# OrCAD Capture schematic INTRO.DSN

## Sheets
1 PAGE2: size A; title: test; rev: A; company: EMA Design Automation; note: 1234567890; note: 225 Tech Park Dr.; note: Rochester, NY 14643
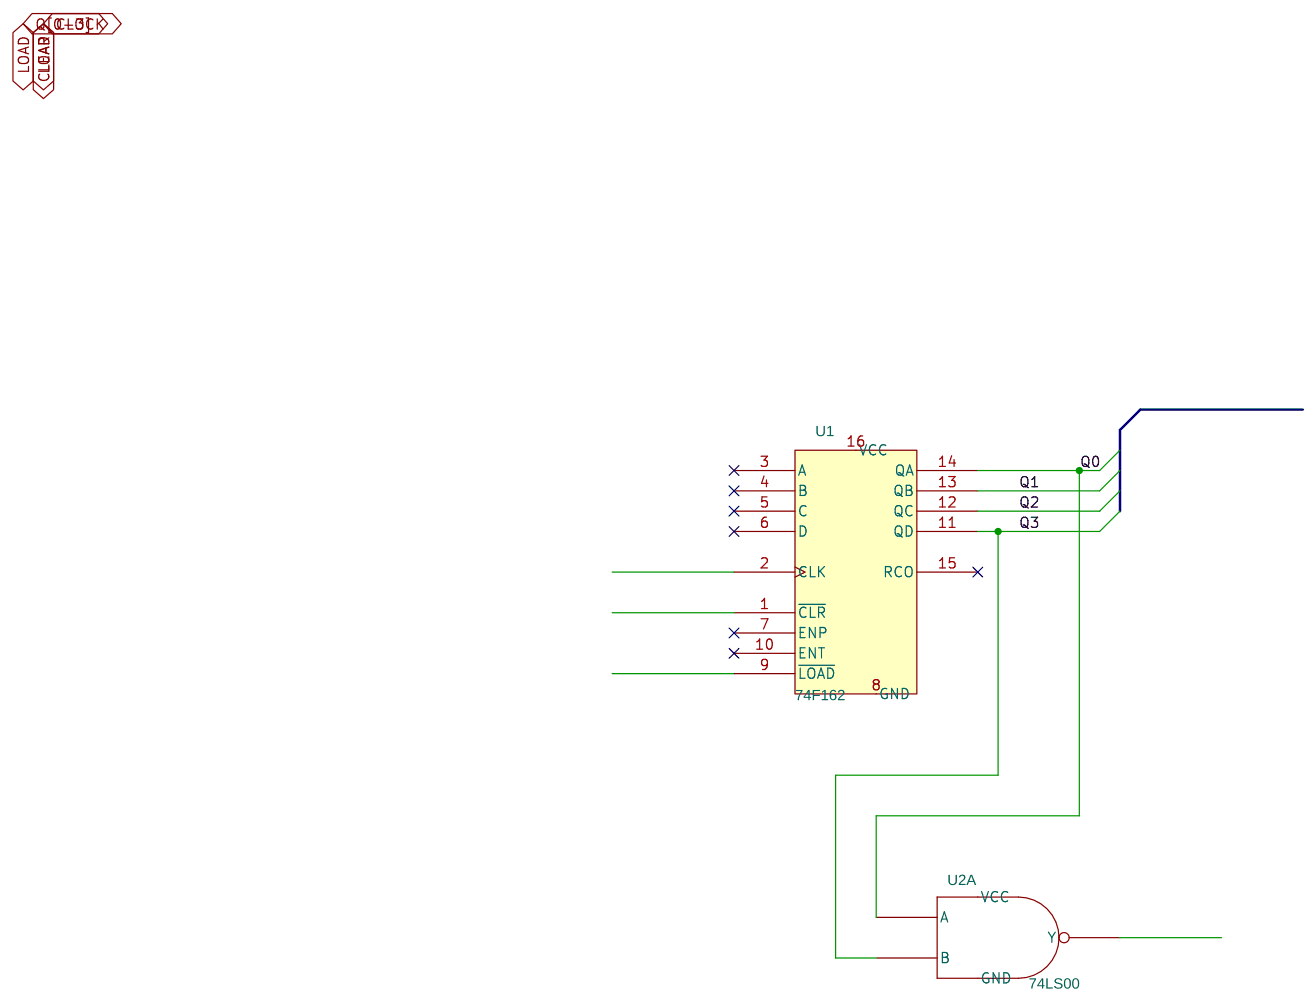
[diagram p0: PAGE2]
2 PAGE1: size A; title: Intro Design; note: Rochester, NY 14623
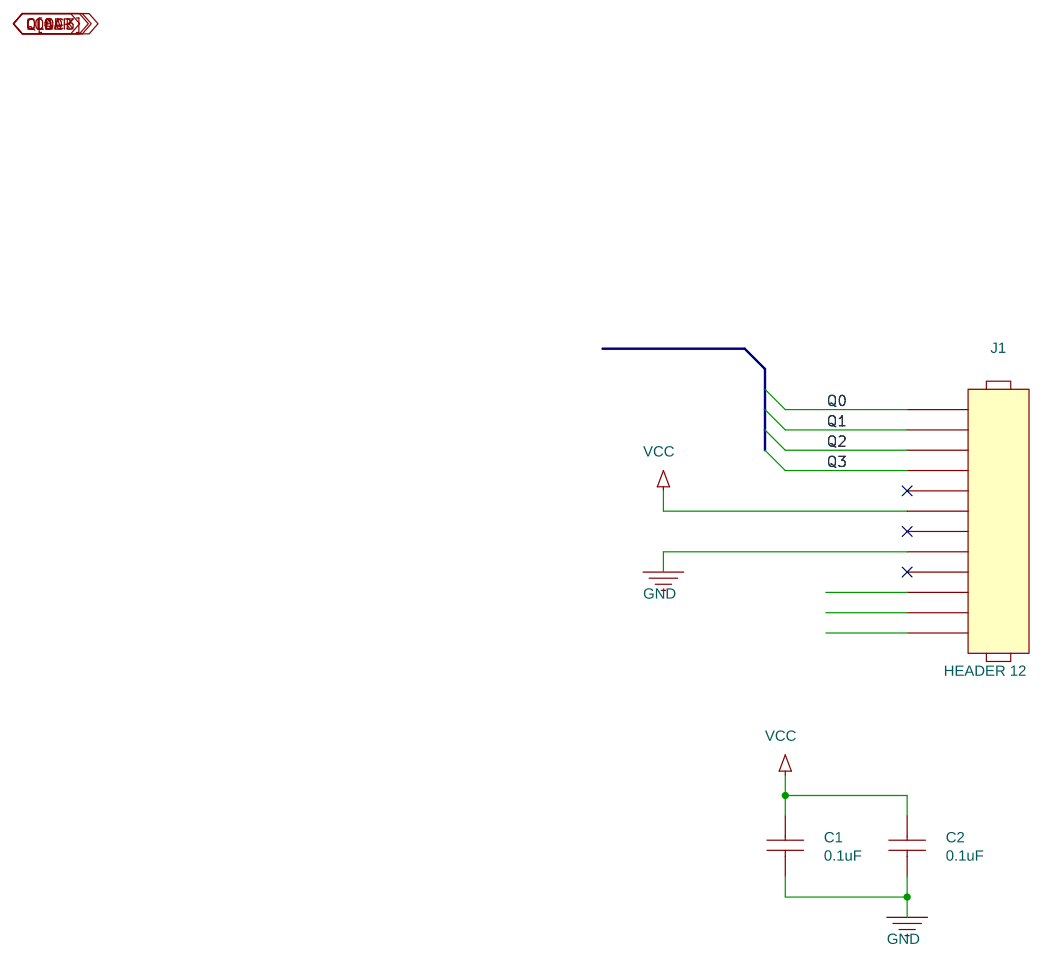
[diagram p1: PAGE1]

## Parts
sheet PAGE1
C1  0.1uF
C2  0.1uF
J1  HEADER 12
sheet PAGE2
U1  74F162
U2  74LS00  (section A)

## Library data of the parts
C1 C2 = CAP_NP
J1 = HEADER_12
U1 = 74F162
U2 = 74LS00

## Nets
GND: C1.2 C2.2 J1.8 U1.8(GND) U2.7(GND)
VCC: C1.1 C2.1 J1.6 U1.16(VCC) U2.14(VCC)
CLEAR: J1.11 U1.1(~{CLR})
CLOCK: J1.12 U1.2(CLK)
LOAD: J1.10 U1.9(~{LOAD}) U2.3(Y)
Q0: J1.1 U1.14(QA) U2.1(A)
Q1: J1.2 U1.13(QB)
Q2: J1.3 U1.12(QC)
Q3: J1.4 U1.11(QD) U2.2(B)

Not connected (* = marked no-connect by the designer): J1 5* 7* 9*; U1 3(A)* 4(B)* 5(C)* 6(D)* 7(ENP)* 10(ENT)* 15(RCO)*
